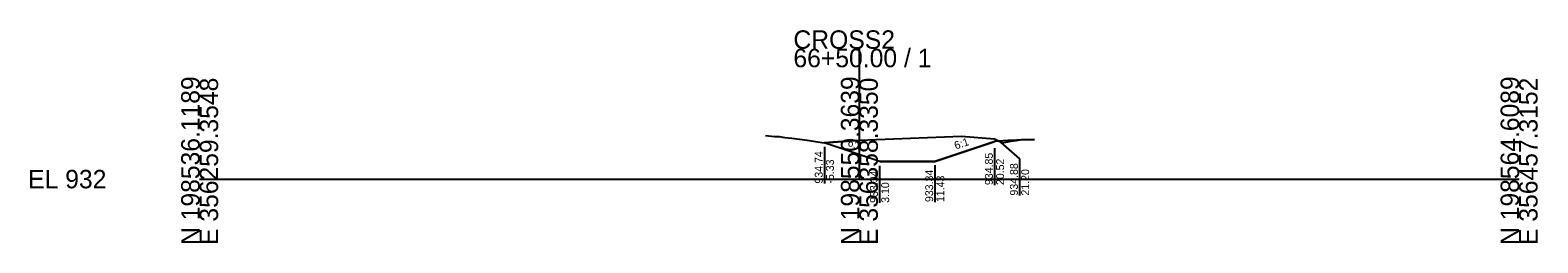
# Model space of a CAD drawing. Extents: x -26 to 203, y -10 to 14021.
# Drawn here: x -25.7 to 202.8, y 7490.3 to 7522.6 of the extents above; entities that cross this region are included whole.
import ezdxf

# ---------------------------------------------------------------- set-up
doc = ezdxf.new("R2010")
doc.units = 0
for name, color, linetype in [('Default', 7, 'Continuous'), ('P_E_XS_Ground', 7, 'Continuous'), ('P_XS', 7, 'Continuous'), ('P_XS_EAR_CommonGrnd', 7, 'Continuous'), ('P_XS_Lane', 7, 'Continuous'), ('P_XS_Rock', 7, 'Continuous')]:
    doc.layers.add(name, color=color, linetype=linetype)

msp = doc.modelspace()

# ---------------------------------------------------------------- linework, layer by layer
at = {"layer": 'Default'}
for p, q in [((100, 7500), (100, 7519.79)), ((0, 7500), (100, 7500)), ((100, 7500), (200, 7500))]:
    msp.add_line(p, q, dxfattribs=at)
at = {"layer": 'P_E_XS_Ground'}
for p, q in [((85.75, 7506.6), (87.12, 7506.49)), ((87.12, 7506.49), (87.83, 7506.48)), ((87.83, 7506.48), (88.38, 7506.38)), ((88.38, 7506.38), (88.68, 7506.32)), ((88.68, 7506.32), (89.76, 7506.2)), ((89.76, 7506.2), (92.08, 7505.93)), ((92.08, 7505.93), (93.63, 7505.65)), ((93.63, 7505.65), (94.67, 7505.49)), ((99.5, 7505.88), (94.67, 7505.49)), ((99.5, 7505.88), (100, 7505.9)), ((100, 7505.9), (115.5, 7506.52)), ((115.5, 7506.52), (120.5, 7506.12)), ((120.5, 7506.12), (121.67, 7505.53)), ((121.67, 7505.53), (122.98, 7505.74)), ((122.98, 7505.74), (123.82, 7505.88)), ((123.82, 7505.88), (124.61, 7506)), ((124.61, 7506), (125.19, 7506.02)), ((125.19, 7506.02), (126.52, 7506.03))]:
    msp.add_line(p, q, dxfattribs=at)
at = {"layer": 'P_XS'}
for p, q in [((122.52, 7505.87), (121.2, 7505.76)), ((126.52, 7506.03), (122.52, 7505.87))]:
    msp.add_line(p, q, dxfattribs=at)
at = {"layer": 'P_XS_EAR_CommonGrnd'}
msp.add_lwpolyline([(120.5, 7506.12), (121.2, 7505.76), (120.52, 7505.71), (111.43, 7502.68), (103.1, 7502.68), (94.67, 7505.49), (99.5, 7505.88), (100, 7505.9), (115.5, 7506.52)], close=True, dxfattribs=at)
at = {"layer": 'P_XS_Lane'}
for p, q in [((103.1, 7502.68), (94.67, 7505.49)), ((111.43, 7502.68), (120.52, 7505.71)), ((121.2, 7505.76), (120.52, 7505.71)), ((103.1, 7502.68), (111.43, 7502.68))]:
    msp.add_line(p, q, dxfattribs=at)
at = {"layer": 'P_XS_Rock'}
for p, q in [((121.44, 7505.56), (124.28, 7503.1)), ((94.69, 7504.91), (94.69, 7499.31)), ((120.48, 7504.68), (120.48, 7499.09)), ((124.28, 7503.1), (124.28, 7497.5)), ((103.06, 7501.99), (103.06, 7496.39)), ((111.43, 7502.1), (111.43, 7496.5))]:
    msp.add_line(p, q, dxfattribs=at)

# ---------------------------------------------------------------- texts
at = {"layer": 'Default'}
for s, p in [('CROSS2', (90, 7519.79)), ('66+50.00 / 1', (90, 7516.99)), ('EL 932', (-26, 7498.6))]:
    msp.add_text(s, height=2.8, dxfattribs=at).set_placement(p)
for s, p in [('N 198536.1189', (0, 7490)), ('E 356259.3548', (2.8, 7490)), ('N 198550.3639', (100, 7490)), ('E 356358.3350', (102.8, 7490)), ('N 198564.6089', (200, 7490)), ('E 356457.3152', (202.8, 7490))]:
    msp.add_text(s, height=2.8, rotation=90, dxfattribs=at).set_placement(p)
at = {"layer": 'P_XS_Rock'}
for s, rotation, p in [('6:1', 341.5651, (98.12, 7505.08)), ('6:1', 18.4349, (114.61, 7504.48)), ('934.74', 90, (94.44, 7499.32)), ('-5.33', 90, (96.14, 7499.32)), ('934.85', 90, (120.23, 7499.09)), ('20.52', 90, (121.93, 7499.09)), ('933.34', 90, (102.81, 7496.39)), ('933.34', 90, (111.18, 7496.51)), ('11.43', 90, (112.88, 7496.51)), ('934.88', 90, (124.03, 7497.5)), ('21.20', 90, (125.73, 7497.5)), ('3.10', 90, (104.51, 7496.39))]:
    msp.add_text(s, height=1.2, rotation=rotation, dxfattribs=at).set_placement(p)

doc.saveas('drawing.dxf')
